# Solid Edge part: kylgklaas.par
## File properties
Author: Mac
Template: Normal.par
Last saved by: Mac
Revision: 13
Application: Solid Edge
Density: 2595,000 kg/m^3
Accuracy: 0,990
Material: Glass, general industrial
Face Style: White (glass)
Fill Style: ANSI36(Marble)
Virtual Style: White (Glass)
Coef. of Thermal Exp: 0.0
Thermal Conductivity: 0.0
Specific Heat: 0.0
Modulus of Elasticity: 0.0
Poission's Ratio: 0.0
Yield Stress: 0.0
Ultimate Stress: 0.0
Elongation: 0.0
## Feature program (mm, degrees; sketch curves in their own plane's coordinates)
sketch for "unnamed Protrusion 1" plane through (0, 0, 0) normal (0, 0, 1) x-axis (1, 0, 0)
extrude "unnamed Protrusion 1" add to key point along +normal
replace surface "unnamed ReplaceSurface 1"
sketch for "unnamed Cutout 1" plane through (17.2231, 15.1706, 0) normal (0, 0, -1) x-axis (1, 0, 0)
  line (59.2433, 13.6622) -> (-66.6267, 13.6622)
  line (-66.6267, 50.0572) -> (-66.6267, 13.6622)
  line (-66.6267, 50.0572) -> (59.2433, 50.0572)
  line (59.2433, 50.0572) -> (59.2433, 13.6622)
extrude "unnamed Cutout 1" cut through along -normal
replace surface "unnamed ReplaceSurface 2"
sketch used by "ExtrudedCutout_9" plane through (0, -47.6819, 0) normal (0, -1, 0) x-axis (1, 0, 0)
  line (50.9356, 3.4307) -> (29.8402, 16.8869)
  bspline degree 3 poles (-6.2658, 3.4307) (-10.4412, 6.5688) (-15.8423, 9.4433) (-22.4691, 12.0543) knots 0 1 multiplicities 4 4
  line (50.9356, 3.4307) -> (-6.2658, 3.4307)
  line (29.8402, 16.8869) -> (11.2912, 16.8869)
  bspline degree 3 poles (11.2912, 16.8869) (-4.1375, 16.9847) (-14.2608, 15.9568) (-22.4691, 12.0543) knots 0 1 multiplicities 4 4
extrude "ExtrudedCutout_9" cut finite 119.4406 along -normal
thinwall "Thinwall_4"  Thickness = 0.08 mm
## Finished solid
Body 1: sheet body, 1 face, 6 edges, 6 vertices.
  Faces by surface: spline 1
  Edges by curve: spline 6
Body 2: solid body, 7 faces, 15 edges, 10 vertices.
  Faces by surface: plane 3, swept 2, offset 1, spline 1
  Edges by curve: intersection 10, line 5
Body 3: sheet body, 1 face, 4 edges, 4 vertices.
  Faces by surface: spline 1
  Edges by curve: spline 4
Bounding box of the edges (mm; curved faces can reach further): 97.793 x 30.322 x 34.114, from (-32.1251, 0, 0) to (65.6678, 30.3223, 34.1136).
Planar faces by outward normal: +z 1, -z 1, oblique 1
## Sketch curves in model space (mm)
line (29.8402, -47.6819, 16.8869) -> (11.2912, -47.6819, 16.8869)
spline (11.2912, -47.6819, 16.8869) -> (-8.2966, -47.6819, 15.9707) -> (-22.4691, -47.6819, 12.0543)
spline (-6.2658, -47.6819, 3.4307) -> (-13.4482, -47.6819, 7.9401) -> (-22.4691, -47.6819, 12.0543)
line (50.9356, -47.6819, 3.4307) -> (-6.2658, -47.6819, 3.4307)
line (50.9356, -47.6819, 3.4307) -> (29.8402, -47.6819, 16.8869)
spline (-7.395, 25.9435, 34.1136) -> (-19.2834, 27.357, 34.1136) -> (-32.1251, 28.4997, 34.1136)
spline (0.7256, 0, 34.1136) -> (-1.5887, 13.3712, 34.1136) -> (-7.395, 25.9435, 34.1136)
spline (65.6678, 0, 0) -> (40.22, 0, 17.3758) -> (0.7256, 0, 34.1136)
line (-32.1251, 0, 0) -> (65.6678, 0, 0)
spline (65.6678, 0, 0) -> (63.3536, 13.3712, 0) -> (57.5472, 25.9435, 0)
spline (57.5472, 25.9435, 0) -> (34.8062, 28.3456, 0) -> (8.6507, 29.8164, 0)
spline (8.6507, 29.8164, 0) -> (-10.9903, 30.2656, 0) -> (-32.1251, 30.2669, 0)
line (-32.1251, 30.2669, 0) -> (-32.1251, 0, 0)
spline (57.5472, 25.9435, 0) -> (32.0994, 25.9435, 17.3758) -> (-7.395, 25.9435, 34.1136)
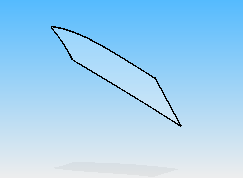
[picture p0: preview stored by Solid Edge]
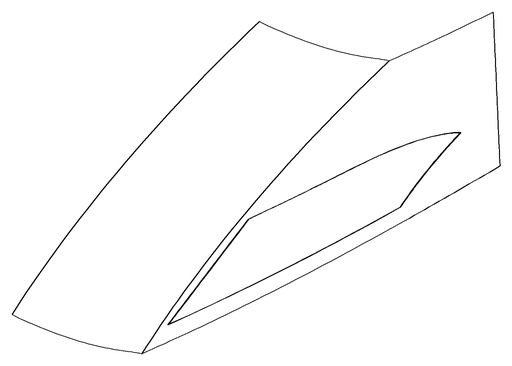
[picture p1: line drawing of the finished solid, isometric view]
